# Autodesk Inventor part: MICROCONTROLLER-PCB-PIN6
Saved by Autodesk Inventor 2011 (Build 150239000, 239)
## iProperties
Created: 2010-06
Part Number: MICROCONTROLLER-PCB-PIN6
Document SubType Name: Modeling
Designer: kurdi
Density: 1 g/cm^3
Author: kurdi
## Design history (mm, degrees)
feature "Base1"
node "NONE"
